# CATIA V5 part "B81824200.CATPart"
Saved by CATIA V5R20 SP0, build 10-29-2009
Part number: B81824200
Revision: 4
Definition: design
Nomenclature: B81824200
Source: made
Description: NOT SPECIFIED
Bounding box of the stored display mesh (mm): x -14 to 14, y -14 to 14, z 0 to 200
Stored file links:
  C:\Users\Raffaele\Desktop\3D X SITO CF\BOLEX\6-PILLAR REF 818\B81824200.CATPart
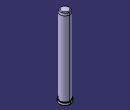
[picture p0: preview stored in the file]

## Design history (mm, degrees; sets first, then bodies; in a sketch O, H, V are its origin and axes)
Body1 "MANIFOLD_SOLID_BREP #370" (main body)
  Solid1: solid without history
